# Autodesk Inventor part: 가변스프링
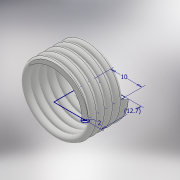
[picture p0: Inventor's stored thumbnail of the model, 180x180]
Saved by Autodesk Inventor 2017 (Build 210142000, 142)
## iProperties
Part Number: 가변스프링
Material: 일반
Document SubType Name: Modeling
Designer: 00-00
Density: 1 g/cm^3
Appearance: 기본값
Author: 00-00
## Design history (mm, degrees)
sketch "스케치1"
  geometry: L1 (0, 0)-(10, 0); L2 (10, 0)-(10, 12.7); L3 (10, 12.7)-(0, 12.7); L4 (0, 12.7)-(0, 0); C1 r 1 at (10, 0)
  constraints: 8 end point, 2 parallel, 1 centre point, 1 coincident, 1 horizontal, 1 perpendicular
  dimensions: "d0" = 10 distance of L2.end L3.end; "d1" = 12.7 distance of L1.end L2.end (derived); "d2" = 2 diameter of C1
feature "코일1" pitch "d3" = 10; turns "d5" = 5; dims "d4" = 12.7 (= d1), "d6" = 0, angle "d7" = 90 deg, angle "d8" = 90 deg, "d9" = 0, "d10" = 0
sketch "스케치2"
  geometry: L1 (-9, 0)-(-11, 0) reference; 1 further point
  constraints: 1 horizontal alignment
extrude "돌출1" cut sketch "스케치2" distance "d11" = 10; taper "d12" = 0 deg
node "작업 평면1"
sketch "스케치3"
  geometry: L1 (-1, 0)-(1, 0) reference; 1 further point
  constraints: 1 horizontal alignment
extrude "돌출2" cut sketch "스케치3" distance "d14" = 10; taper "d15" = 0 deg
node "솔리드1"
node "절단 모서리 투영1"
node "절단 모서리 투영2"
other parameters: "d13" = 90 deg
